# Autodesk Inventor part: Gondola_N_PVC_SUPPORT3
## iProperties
Shininess: 64.0
Length Units: 11272
Angle Units: 11279
Time Units: 11290
Mass Units: 11286
Length Display Precision: 3
Angle Display Precision: 2
Compacted: True
Part Number: Gondola_N_PVC_SUPPORT3
Document SubType Name: Modeling
Created: 2004-12
Designer: John Blackburn
Material: PVC-Piping
Manufacturer: Standard
Standards Organization: Custom
Density: 0.0
Volumn: 0.0
Area: 0.0
PropertySet Name: Model Information
Control State: 0
Master: False
Checked Out: False
Author: John Blackburn
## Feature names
1. Extrusion1
2. Hole1
3. Hole2
4. Hole3
